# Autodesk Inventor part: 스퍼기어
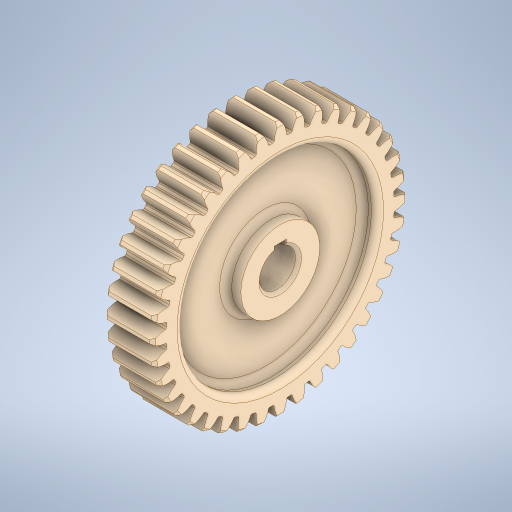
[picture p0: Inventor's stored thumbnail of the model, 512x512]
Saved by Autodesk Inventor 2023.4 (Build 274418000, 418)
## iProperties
Created: 2024-04
Part Number: 스퍼기어
Material: 강철, 합금
Document SubType Name: Modeling
Designer: Edu03
Density: 7.73 g/cm^3
Appearance: 기본값
Author: jhkim
Sending System: Autodesk Inventor 2025
Preprocessor: ST-DEVELOPER v20
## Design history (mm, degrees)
feature "솔리드1"
node "솔리드2"
